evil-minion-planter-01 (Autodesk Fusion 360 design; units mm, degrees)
parameter "nozzleDiameter" = 0.4
parameter "wallThickness" = 2.4 (= "nozzleDiameter * numberOfPerimeter")
parameter "firstLayerHeight" = 0.2
parameter "layerHeight" = 0.2
sketch "Sketch planter" plane through (0, 0, 0) normal (0, 1, 0) x axis (1, 0, 0)
  line L1 (0, -180) -> (0, 0)
  line L2 (70.3946, -138) -> (73, -180)
  line L3 (64.3946, -138) -> (70.3946, -138)
  line L4 (45, 0) -> (64.3946, -138)
  line L5 (0, 0) -> (45, 0)
  line L6 (73, -180) -> (68.2, -180)
  line L7 (59.5946, -144) -> (40.2, -6)
  line L8 (65.9668, -144) -> (59.5946, -144)
  line L9 (68.2, -180) -> (65.9668, -144)
  line L10 (53.8433, -80) -> (56.2433, -80)
  line L11 (57.2162, -104) -> (53.8433, -80)
  line L12 (59.6162, -104) -> (57.2162, -104)
  line L13 (45.8432, -6) -> (40.2, -6)
  line L14 (0, -6) -> (40.2, -6)
  line L15 (0, 0) -> (0, -6)
  line L16 (0, -92) -> (55.5298, -92)
  line L17 (42.6, -6) -> (53.8433, -80)
  line L18 (62.8379, -144) -> (57.2162, -104)
  point P1 (0, 0)
  point P2 (0, 0)
  point P8 (0, 0)
  point P3 (0, -180)
  point P10 (68.2, -180)
  point P13 (56.2433, -80)
  point P16 (59.6162, -104)
  point P18 (0, -6)
  point P19 (0, 0)
  point P20 (55.5298, -92)
  point P21 (0, -92)
  point P17 (45.8432, -6)
  point P23 (62.8379, -144)
  point P7 (45, 0)
  point P4 (73, -180)
  point P5 (70.3946, -138)
  point P6 (64.3946, -138)
  point P9 (40.2, -6)
  point P11 (59.5946, -144)
  point P14 (53.8433, -80)
  point P22 (42.6, -6)
  coincident P1 P2
  vertical L1
  coincident P1 P8
  perpendicular L1 L5
  horizontal L3
  horizontal L6
  horizontal P3 P10
  parallel L4 L7
  horizontal L8
  parallel L2 L9
  coincident L4 P13
  coincident L4 P16
  horizontal L10
  horizontal L12
  parallel L4 L11
  horizontal L13
  coincident L1 P18
  perpendicular L1 L14
  coincident P1 P19
  midpoint L11 P20
  coincident L1 P21
  perpendicular L1 L16
  coincident L4 P17
  coincident L8 P23
  collinear L11 L18
  dimension "potBottomRadius" distance P7 P8 = 45
  dimension "potHeight" distance P2 P3 = 180
  dimension "potTopRadius" distance P3 P4 = 73
  dimension "potTopOffset" distance P5 P6 = 6
  dimension "potBottomAngle" angle L4 L5 = 98
  dimension "potTopHeight" distance P4 P5 = 42
  dimension "d11" distance P7 P9 = 4.8 (= "wallThickness * 2")
  dimension "d19" distance P6 P11 = 4.8 (= "wallThickness * 2")
  dimension "d20" distance P4 P10 = 4.8 (= "wallThickness * 2")
  dimension "bandHeight" distance P13 P16 = 24
  dimension "d22" distance P13 P14 = 2.4 (= "wallThickness")
  dimension "bottomHeight" distance P7 P9 = 6
  dimension "d65" distance P1 P21 = 92 (= "eyeCenterOffset")
  dimension "d119" distance P9 P22 = 2.4 (= "wallThickness")
revolve "Revolve1" sketch "Sketch planter" AlongAngle 360 bodies "Planter"
chamfer "Chamfer1" distance 6 named "topOffsetOuterChamfer" distance 6.37 named "topOffsetInnerChamfer" distance 1 Rotate Angle 60 named "chamferAngle" Rotate Angle 60 (= "chamferAngle") Rotate Angle 60 (= "chamferAngle")
sketch "Sketch Eye" plane through (0, 0, 0) normal (0, 1, 0) x axis (1, 0, 0)
  line L1 (20, -92) -> (-20, -92)
  line L2 (-19.192, -94) -> (-19.8997, -94)
  line L3 (19.8997, -94) -> (-19.192, -94)
  circle C1 centre (0, -92) radius 33.5
  circle C2 centre (0, -92) radius 30.5
  circle C3 centre (0, -92) radius 23
  circle C4 centre (0, -92) radius 20
  circle C5 centre (0, -92) radius 12
  circle C6 centre (0, -92) radius 10
  circle C7 centre (0, -92) radius 5.5
  point P8 (-20, -92)
  point P9 (20, -92)
  point P10 (-19.8997, -94)
  point P12 (19.8997, -94)
  point P5 (0, -92)
  point P7 (0, -92)
  point P14 (0, 0)
  point P3 (0, -92)
  concentric C2 C4
  concentric C2 C6
  concentric C4 C7
  coincident C4 P8
  coincident C4 P9
  horizontal L1
  coincident C4 P10
  parallel L1 L2
  coincident C4 P12
  horizontal L3
  coincident P5 L1
  vertical P7 P14
  dimension "glassesOuterDiameter" diameter C1 = 67
  dimension "glassesInnerDiameter" diameter C3 = 46
  dimension "eyeDiameter" diameter C5 = 24
  dimension "pupileDiameter" diameter C7 = 11
  dimension "eyelidFrameThickness" distance L1 L3 = 2
  dimension "glassesFrameThickness" distance C1 C2 = 3
  dimension "d57" distance C3 C4 = 3 (= "glassesFrameThickness")
  dimension "eyeRingThickness" distance C5 C6 = 2
  dimension "eyeCenterOffset" distance P3 P14 = 92
extrude "Extrude1" sketch "Sketch Eye" blind 3.6 (= "--wallThickness * 1.5") bodies "Glasses outer ring and band", "Glasses inner ring and eye"
extrude "Extrude2" sketch "Sketch Eye" profile of C2 C3 blind 3.6 (= "wallThickness * 1.5") bodies "Body glasses"
extrude "Extrude2" sketch "Sketch Eye" profile of C4 C5 L1 blind 3.6 (= "wallThickness * 1.5") bodies "Body eye"
revolve "Revolve1" sketch "Sketch planter" AlongAngle 240 named "bandRevolveAnglePartOne"
revolve "Revolve2" sketch "Sketch planter" AlongAngle -59 named "bandRevolveAnglePartTwo"
combine "Combine3"
revolve "Revolve1" sketch "Sketch planter" AlongAngle 360
combine "Combine3"
sketch "Sketch Mouth" plane through (0, 0, 0) normal (0, 1, 0) x axis (-1, 0, 0)
  curve K1 (18.3694, 38.8324) -> (26.0777, 35.6978)
  curve K2 (27.2282, 40.2445) -> (26.0777, 35.6978)
  curve K3 (24.2766, 43.1284) -> (27.2282, 40.2445)
  curve K4 (21.3256, 43.7649) -> (24.2766, 43.1284)
  curve K5 (19.633, 42.6566) -> (21.3256, 43.7649)
  curve K6 (18.3694, 38.8324) -> (19.633, 42.6566)
  curve K7 (8.8731, 41.1665) -> (18.3694, 38.8324)
  curve K8 (18.9187, 43.2594) -> (18.3694, 38.8324)
  curve K9 (16.9974, 46.0918) -> (18.9187, 43.2594)
  curve K10 (15.1652, 47.1932) -> (16.9974, 46.0918)
  curve K11 (12.0408, 46.5638) -> (15.1652, 47.1932)
  curve K12 (10.4788, 44.8493) -> (12.0408, 46.5638)
  curve K13 (8.8731, 41.1665) -> (10.4788, 44.8493)
  curve K14 (28.6915, 31.1726) -> (28.6915, 31.1726)
  curve K15 (19.2845, 38.8948) -> (28.6915, 31.1726)
  curve K16 (-11.4556, 40.1874) -> (19.2845, 38.8948)
  curve K17 (-32.2053, 37.1847) -> (-11.4556, 40.1874)
  curve K18 (-37.6765, 40.7485) -> (-32.2053, 37.1847)
  curve K19 (-36.6067, 38.1949) -> (-37.6765, 40.7485)
  curve K20 (-38.0602, 43.7396) -> (-36.6067, 38.1949)
  curve K21 (-27.5386, 45.0079) -> (-38.0602, 43.7396)
  curve K22 (8.4284, 43.0616) -> (-27.5386, 45.0079)
  curve K23 (25.4955, 37.3951) -> (8.4284, 43.0616)
  curve K24 (29.8893, 33.4007) -> (25.4955, 37.3951)
  curve K25 (33.0021, 30.7405) -> (29.8893, 33.4007)
  curve K26 (28.6915, 31.1726) -> (33.0021, 30.7405)
  curve K27 (-30.0416, 43.9076) -> (-23.0423, 44.1869)
  curve K28 (-24.4376, 53.7394) -> (-23.0423, 44.1869)
  curve K29 (-25.2975, 54.59) -> (-24.4376, 53.7394)
  curve K30 (-25.6809, 55.9205) -> (-25.2975, 54.59)
  curve K31 (-30.4496, 57.7496) -> (-25.6809, 55.9205)
  curve K32 (-37.6309, 57.4808) -> (-30.4496, 57.7496)
  curve K33 (-35.8954, 54.0369) -> (-37.6309, 57.4808)
  curve K34 (-30.0416, 43.9076) -> (-35.8954, 54.0369)
  curve K35 (-23.0423, 44.1869) -> (-9.365, 43.5533)
  curve K36 (-8.4172, 51.7974) -> (-9.365, 43.5533)
  curve K37 (-12.0356, 58.6407) -> (-8.4172, 51.7974)
  curve K38 (-12.9784, 58.8764) -> (-12.0356, 58.6407)
  curve K39 (-14.2763, 58.837) -> (-12.9784, 58.8764)
  curve K40 (-23.4814, 58.6403) -> (-14.2763, 58.837)
  curve K41 (-23.4814, 55.1416) -> (-23.4814, 58.6403)
  curve K42 (-23.0423, 44.1869) -> (-23.4814, 55.1416)
  curve K43 (-6.7174, 43.3223) -> (8.8731, 41.1665)
  curve K44 (10.1089, 47.0368) -> (8.8731, 41.1665)
  curve K45 (9.2021, 49.6324) -> (10.1089, 47.0368)
  curve K46 (7.51, 50.4966) -> (9.2021, 49.6324)
  curve K47 (6.0546, 50.3382) -> (7.51, 50.4966)
  curve K48 (4.6785, 49.3537) -> (6.0546, 50.3382)
  curve K49 (4.3641, 48.96) -> (4.6785, 49.3537)
  curve K50 (3.8523, 49.5104) -> (4.3641, 48.96)
  curve K51 (-0.8323, 53.9127) -> (3.8523, 49.5104)
  curve K52 (-3.1141, 54.2651) -> (-0.8323, 53.9127)
  curve K53 (-5.7095, 53.083) -> (-3.1141, 54.2651)
  curve K54 (-7.3982, 49.3053) -> (-5.7095, 53.083)
  curve K55 (-6.7174, 43.3223) -> (-7.3982, 49.3053)
  curve K56 (20.2685, 38.2049) -> (24.1388, 36.1884)
  curve K57 (10.7064, 40.3672) -> (16.3847, 39.0787)
  curve K58 (-4.7302, 43.5484) -> (6.916, 41.5785)
  line L1 (-4.6817, 43.1215) -> (-4.7302, 43.5484)
  curve K59 (-21.0439, 44.267) -> (-11.3519, 43.7817)
  line L2 (-11.3607, 43.7054) -> (-11.3519, 43.7817)
  curve K60 (-33.6472, 55.0256) -> (-25.0213, 43.8978)
  curve K61 (-28.3099, 44.9083) -> (-33.6472, 55.0256)
  line L3 (-27.8328, 44.0827) -> (-28.3099, 44.9083)
  line L4 (6.9058, 41.53) -> (6.916, 41.5785)
  line L5 (-21.0397, 44.1625) -> (-21.0439, 44.267)
  point P34 (28.6915, 31.1726)
  point P35 (28.6915, 31.1726)
  point P32 (18.3694, 38.8324)
  point P29 (8.8731, 41.1665)
  point P6 (-6.7174, 43.3223)
  point P2 (-9.365, 43.5533)
  point P47 (-30.0416, 43.9076)
  point P27 (26.0777, 35.6978)
  point P60 (-4.6817, 43.1215)
  point P63 (-11.3607, 43.7054)
  point P13 (-23.0423, 44.1869)
  point P67 (-27.8328, 44.0827)
  point P68 (6.9058, 41.53)
  point P69 (-21.0397, 44.1625)
  coincident P34 P35
  coincident P32 K14
  coincident P29 K14
  coincident P6 K14
  coincident P2 K14
  coincident P47 K14
  coincident P27 K14
  coincident K14 P60
  coincident K14 P63
  coincident P13 K14
  coincident K14 P67
  coincident K14 P68
  coincident K14 P69
  dimension "toothOffset" = -2
  dimension "d94" = -2 (= "toothOffset")
  dimension "d95" = -2 (= "toothOffset")
  dimension "d96" = -2 (= "toothOffset")
  dimension "d97" = -2 (= "toothOffset")
  dimension "d105" = -2 (= "toothOffset")
  dimension "d106" = -2 (= "toothOffset")
  dimension "d107" = -2 (= "toothOffset")
  dimension "d108" = -2 (= "toothOffset")
  dimension "d109" = -2 (= "toothOffset")
extrude "Extrude6" sketch "Sketch Mouth" profile of K14 K56 K57 K58 L1 K59 L2 K61 L3 L4 L5 blind 2.4 (= "wallThickness") bodies "Tooth 3", "Tooth 4", "Tooth  2", "Tooth 5", "Tooth 1"
extrude "Extrude4" sketch "Sketch Mouth" profile of K1 K7 K14 K27 K35 K43 K56 K57 K58 L1 K59 L2 K61 L3 L4 L5 blind 2.4 (= "wallThickness") bodies "Mouth and tooth frames"
fillet "Fillet5" radius 0.4
combine "Combine7"
sketch "Sketch Coaster" plane through (0, 0, 0) normal (0, 1, 0) x axis (1, 0, 0)
  line L1 (45, 0) -> (-45, 0)
  line L2 (57.4, 6) -> (0, 6)
  line L3 (59.4378, -8.5) -> (57.4, 6)
  line L4 (65.4378, -8.5) -> (59.4378, -8.5)
  line L5 (66.0892, -19) -> (65.4378, -8.5)
  line L6 (57.6703, -19) -> (66.0892, -19)
  line L7 (55, 0) -> (57.6703, -19)
  line L8 (0, 0) -> (55, 0)
  line L9 (0, 6) -> (0, 0)
  line L10 (45, 0) -> (56.2433, -80)
  line L11 (-56.2433, -80) -> (-45, 0)
  line L12 (70.3946, -138) -> (72.8928, -178.2713)
  line L13 (-72.8928, -178.2713) -> (-70.3946, -138)
  point P1 (0, 0)
  point P11 (0, 0)
  point P4 (0, 6)
  point P3 (45, 0)
  point P10 (55, 0)
  point P5 (57.4, 6)
  point P8 (66.0892, -19)
  point P6 (59.4378, -8.5)
  point P7 (65.4378, -8.5)
  horizontal L2
  parallel L2 L4
  parallel L4 L6
  parallel L6 L8
  perpendicular L2 L9
  coincident P1 P11
  parallel L5 L12
  parallel L7 L10
  parallel L3 L7
  dimension "d124" distance P4 P11 = 6 (= "bottomHeight")
  dimension "planterCosterSpacing" distance P3 P10 = 10
  dimension "d126" distance P5 P10 = 2.4 (= "wallThickness")
  dimension "costerHeight" distance P5 P8 = 25
  dimension "d128" distance P6 P7 = 6 (= "potTopOffset")
  dimension "d129" distance P7 P8 = 10.5 (= "potTopHeight / 4")
revolve "Revolve1" sketch "Sketch Coaster" AlongAngle 360
chamfer "Chamfer1" distance 6 distance 1 Rotate Angle 60 (= "chamferAngle") Rotate Angle 60 (= "chamferAngle")
sketch "Sketch Drainage" plane through (0, 0, 0) normal (0, 0, 1) x axis (-1, 0, 0)
  line L1 (-1, 0) -> (1, 0)
  line L2 (-1, 15) -> (-1, 0)
  line L3 (1, 15) -> (-1, 15)
  line L4 (1, 0) -> (1, 15)
  line L5 (-27.5, 47.6314) -> (0, 0)
  circle C1 centre (0, 0) radius 55
  circle C2 centre (-9, 15.5885) radius 1.5
  point P1 (0, 0)
  point P6 (0, 0)
  point P7 (-27.5, 47.6314)
  point P9 (-9, 15.5885)
  point P2 (1, 0)
  point P3 (-1, 0)
  point P4 (-1, 15)
  horizontal L1
  vertical L2
  horizontal L3
  vertical L4
  midpoint P1 L1
  coincident P1 P6
  coincident P7 C1
  coincident L5 P9
  dimension "spacerWidth" distance P2 P3 = 2
  dimension "spacerLength" distance P3 P4 = 15
  dimension "d165" angle L2 L5 = 30 (= "360 deg / numberOfSpacer")
  dimension "drainageHoleDiameter" diameter C2 = 3
  dimension "drainageHoleOffset" distance P1 P9 = 18
extrude "Extrude1" add sketch "Sketch Drainage" profile of L1 L2 L3 L4 along normal blind 3 named "spacerHeight"
chamfer "Chamfer2" distance 0.5 named "spacerChamfer"
rectangular_pattern "R-Pattern1" uSpaceDistance 44 named "spacerDistance" vSpaceDistance 0
circular_pattern "C-Pattern1" countU 12 named "numberOfSpacer" TotalAngle 360
extrude "Extrude2" cut sketch "Sketch Drainage" profile of C2 to an object
rectangular_pattern "R-Pattern1" uSpaceDistance 17 vSpaceDistance 0
circular_pattern "C-Pattern1" countU 12 TotalAngle 360
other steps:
revolve "Revolve1" sketch "Sketch planter" AlongAngle 360
revolve "Revolve3" sketch "Sketch planter" AlongAngle 360
create_component "CreateComponent2"
create_component "CreateComponent4"
create_component "CreateComponent5"
create_component "CreateComponent6"
create_component "CreateComponent7"
named bodies: "Planter", "Glasses outer ring and band", "Glasses inner ring and eye", "Body glasses", "Body eye", "Tooth 3", "Tooth 4", "Tooth  2", "Tooth 5", "Tooth 1", "Mouth and tooth frames"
